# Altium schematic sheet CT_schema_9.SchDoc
size 386 x 278 mm
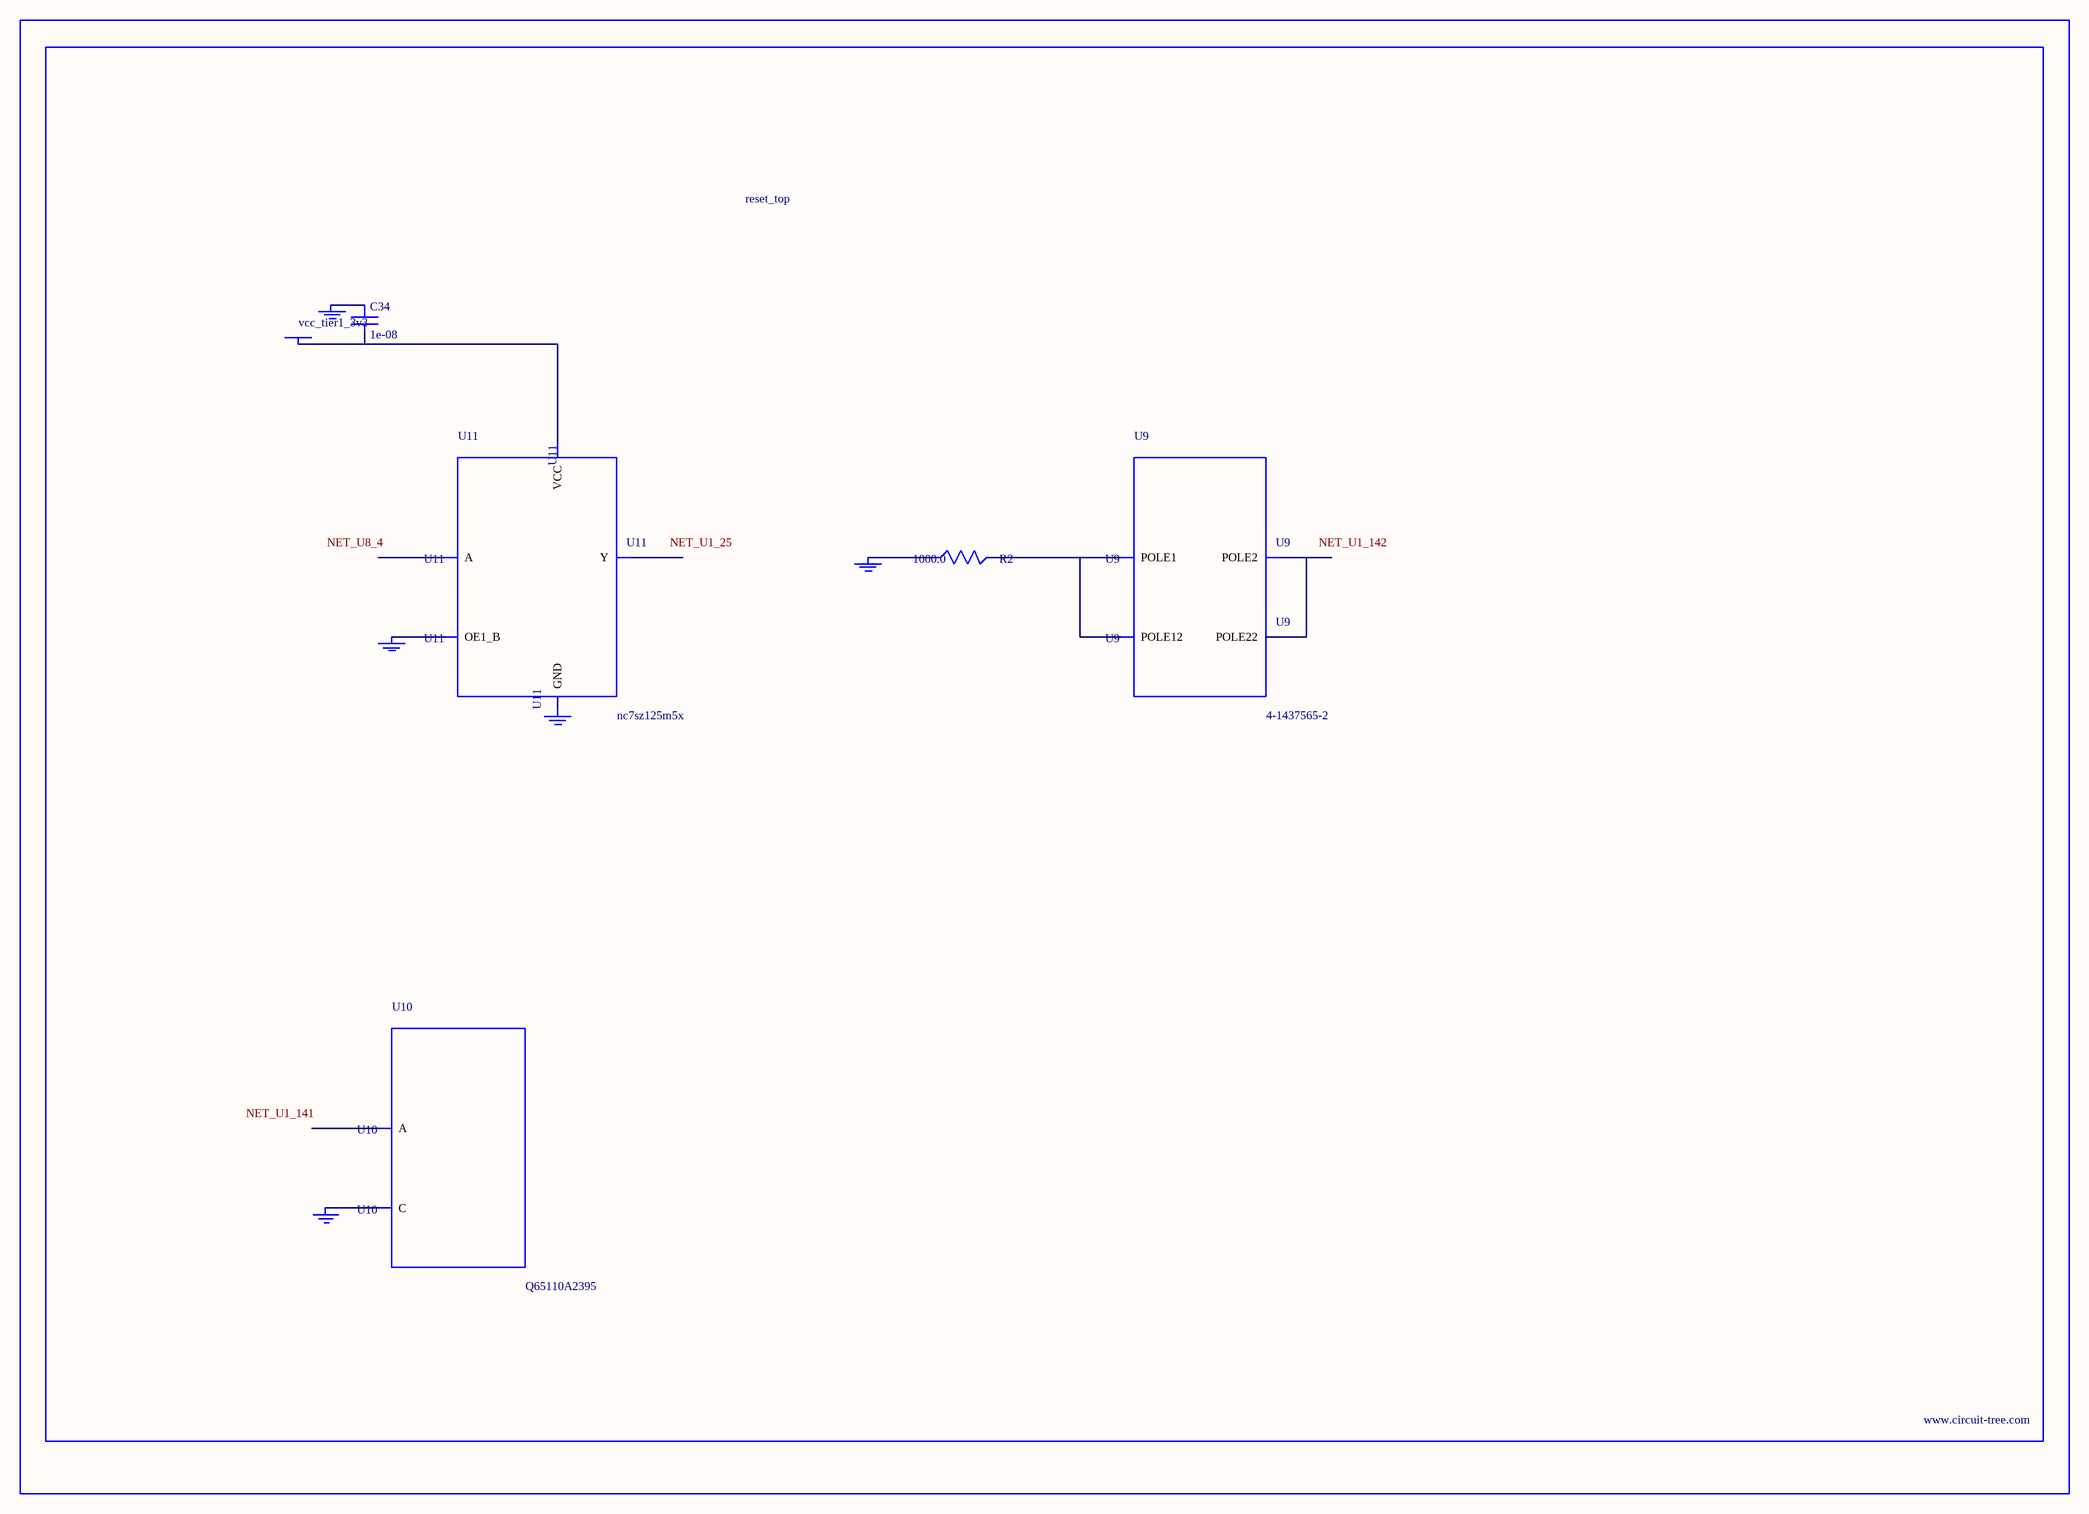
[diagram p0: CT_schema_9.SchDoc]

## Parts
BORDER8  (no value)
C34  1e-08  [C0402]
GND_INSTANCE_8_0  (no value)
GND_INSTANCE_8_1  (no value)
GND_INSTANCE_8_2  (no value)
GND_INSTANCE_8_3  (no value)
GND_INSTANCE_8_4  (no value)
POWER_INSTANCE_8_0  vcc_tier1_3v3
R2  1000.0  [R0603]
U9  4-1437565-2  [SW_4-1437565-2]
U10  Q65110A2395  [LGM67K-G1J2-24-Z]
U11  nc7sz125m5x  [NC7SZ125M5X]

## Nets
NetC34_1: C34.1 GND_INSTANCE_8_2.0(GND)
NetC34_2: C34.2 POWER_INSTANCE_8_0.0(PWR) U11.5(VCC)
NetGND_INSTANCE_8_0_0: GND_INSTANCE_8_0.0(GND) R2.1
NetGND_INSTANCE_8_1_0: GND_INSTANCE_8_1.0(GND) U10.C
NetGND_INSTANCE_8_3_0: GND_INSTANCE_8_3.0(GND) U11.1(OE1_B)
NetGND_INSTANCE_8_4_0: GND_INSTANCE_8_4.0(GND) U11.3(GND)
NetR2_2: R2.2 U9.1(POLE1) U9.2(POLE12)
NetU9_3: U9.3(POLE2) U9.4(POLE22)

Not connected (* = marked no-connect by the designer): U10 A; U11 2(A) 4(Y)

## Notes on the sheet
- Labels drawn without touching a wire or pin: NET_U1_25, NET_U1_141, NET_U1_142, NET_U8_4

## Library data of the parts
BORDER8 = BORDER_PAGE8
C34 = C0402C103K3RAC
GND_INSTANCE_8_0-GND_INSTANCE_8_4 = GND
POWER_INSTANCE_8_0 = PWR
R2 = RC0603JR-071KL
